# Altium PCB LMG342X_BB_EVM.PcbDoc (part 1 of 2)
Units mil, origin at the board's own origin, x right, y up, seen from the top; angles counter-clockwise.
Board outline 6400 x 3655 mil, 2 copper layers (Top Layer, Bottom Layer), stack 61.2 mil thick; 157 components, 63 nets, 278 pads, 411 vias.
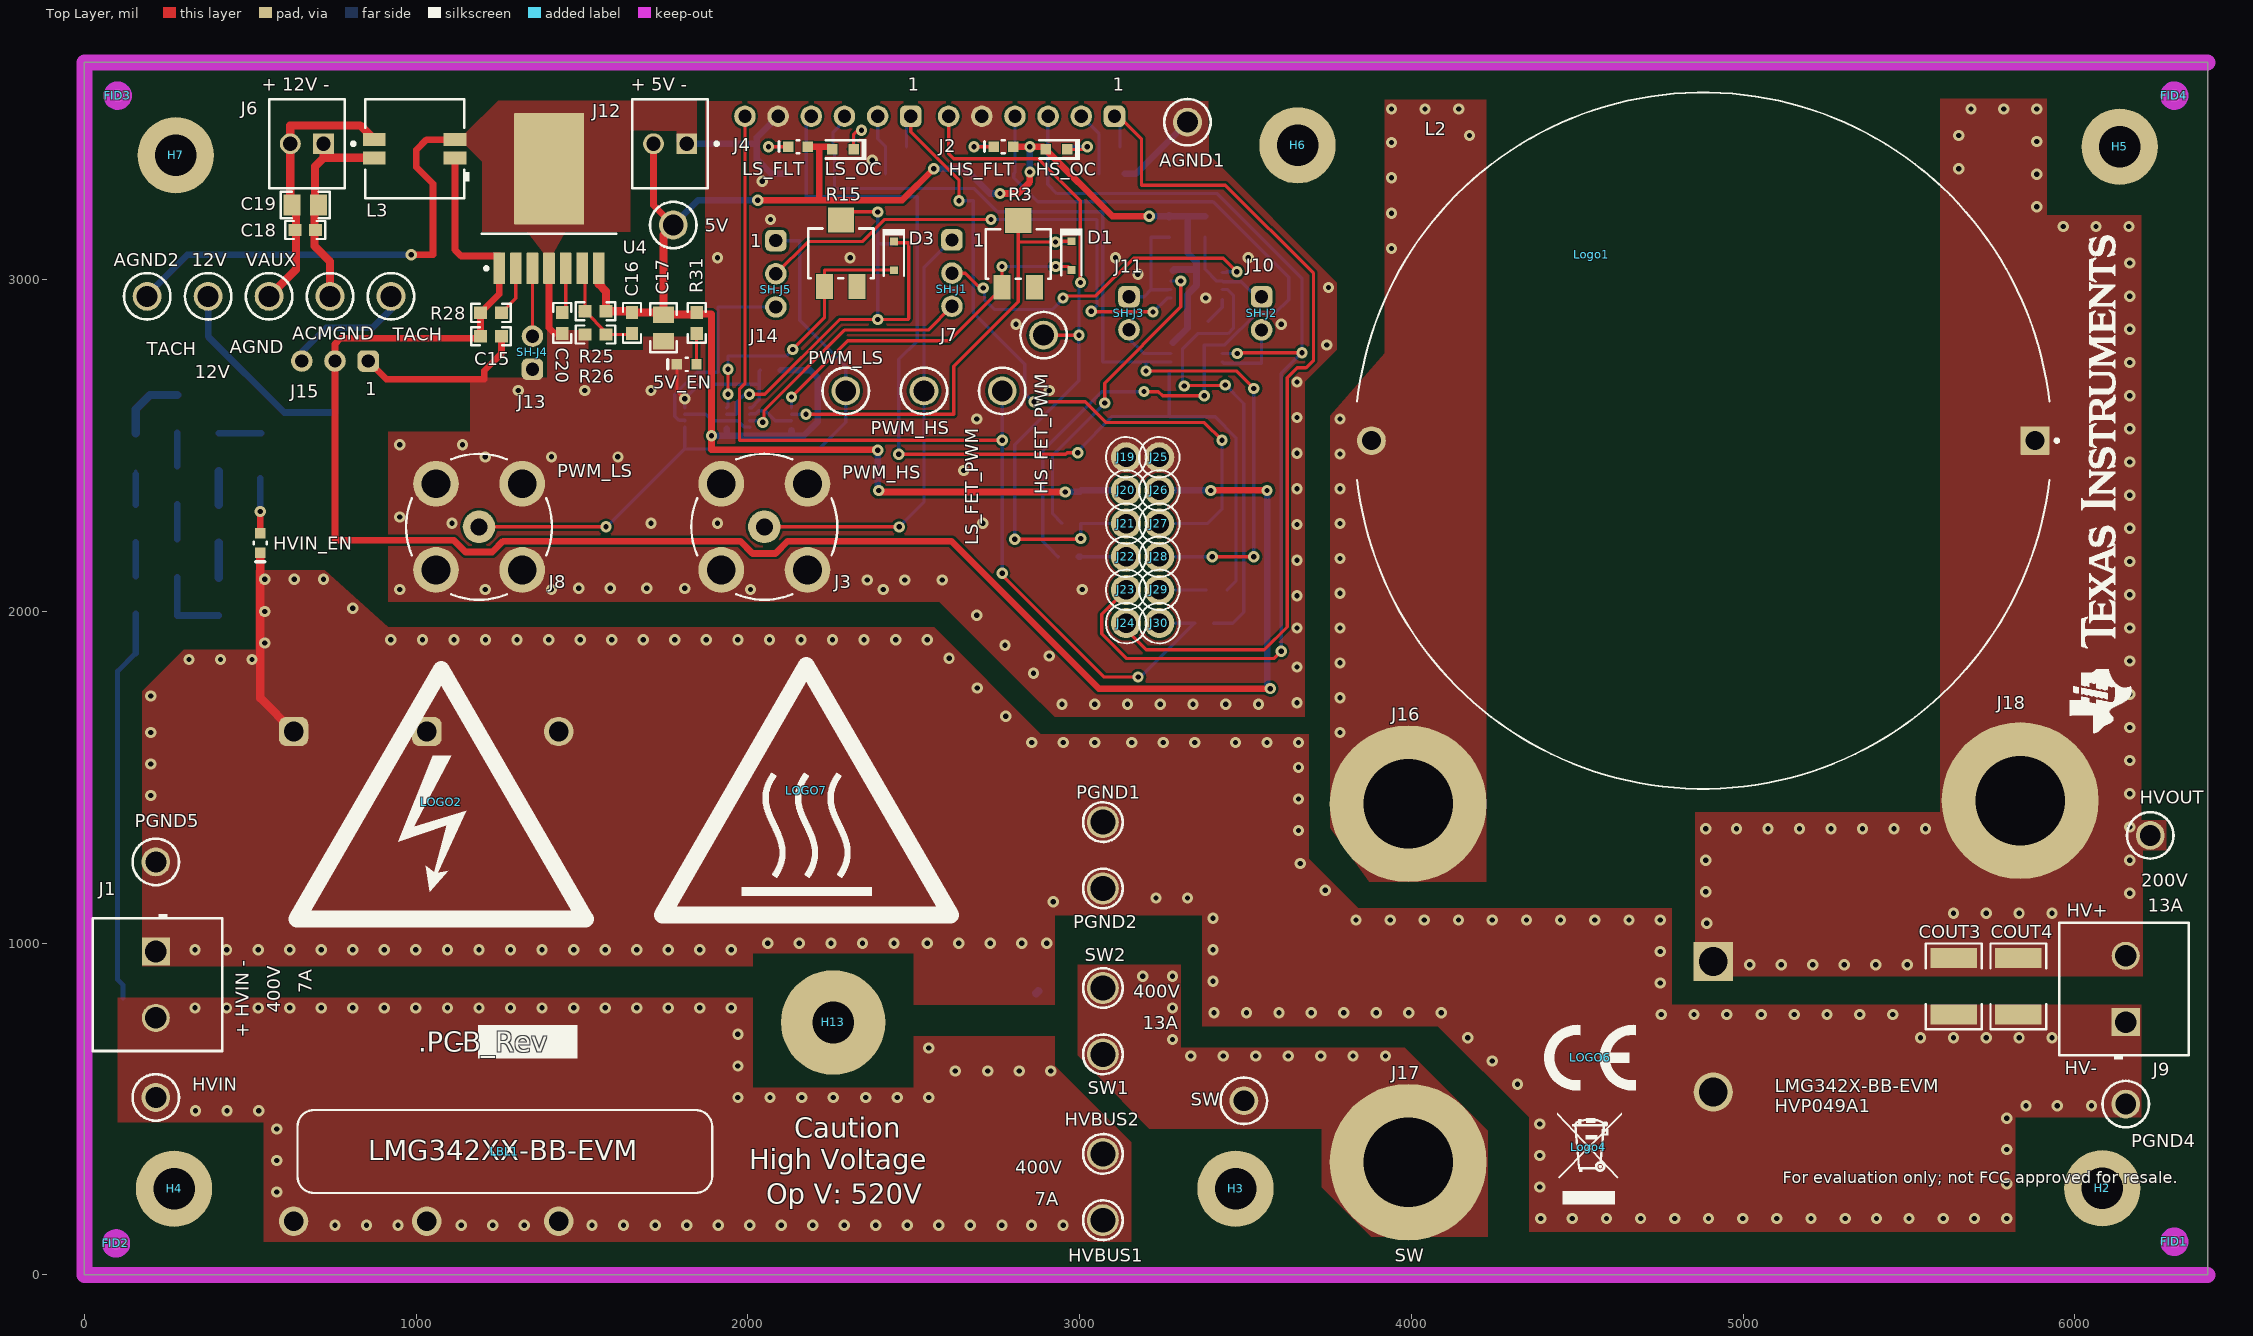
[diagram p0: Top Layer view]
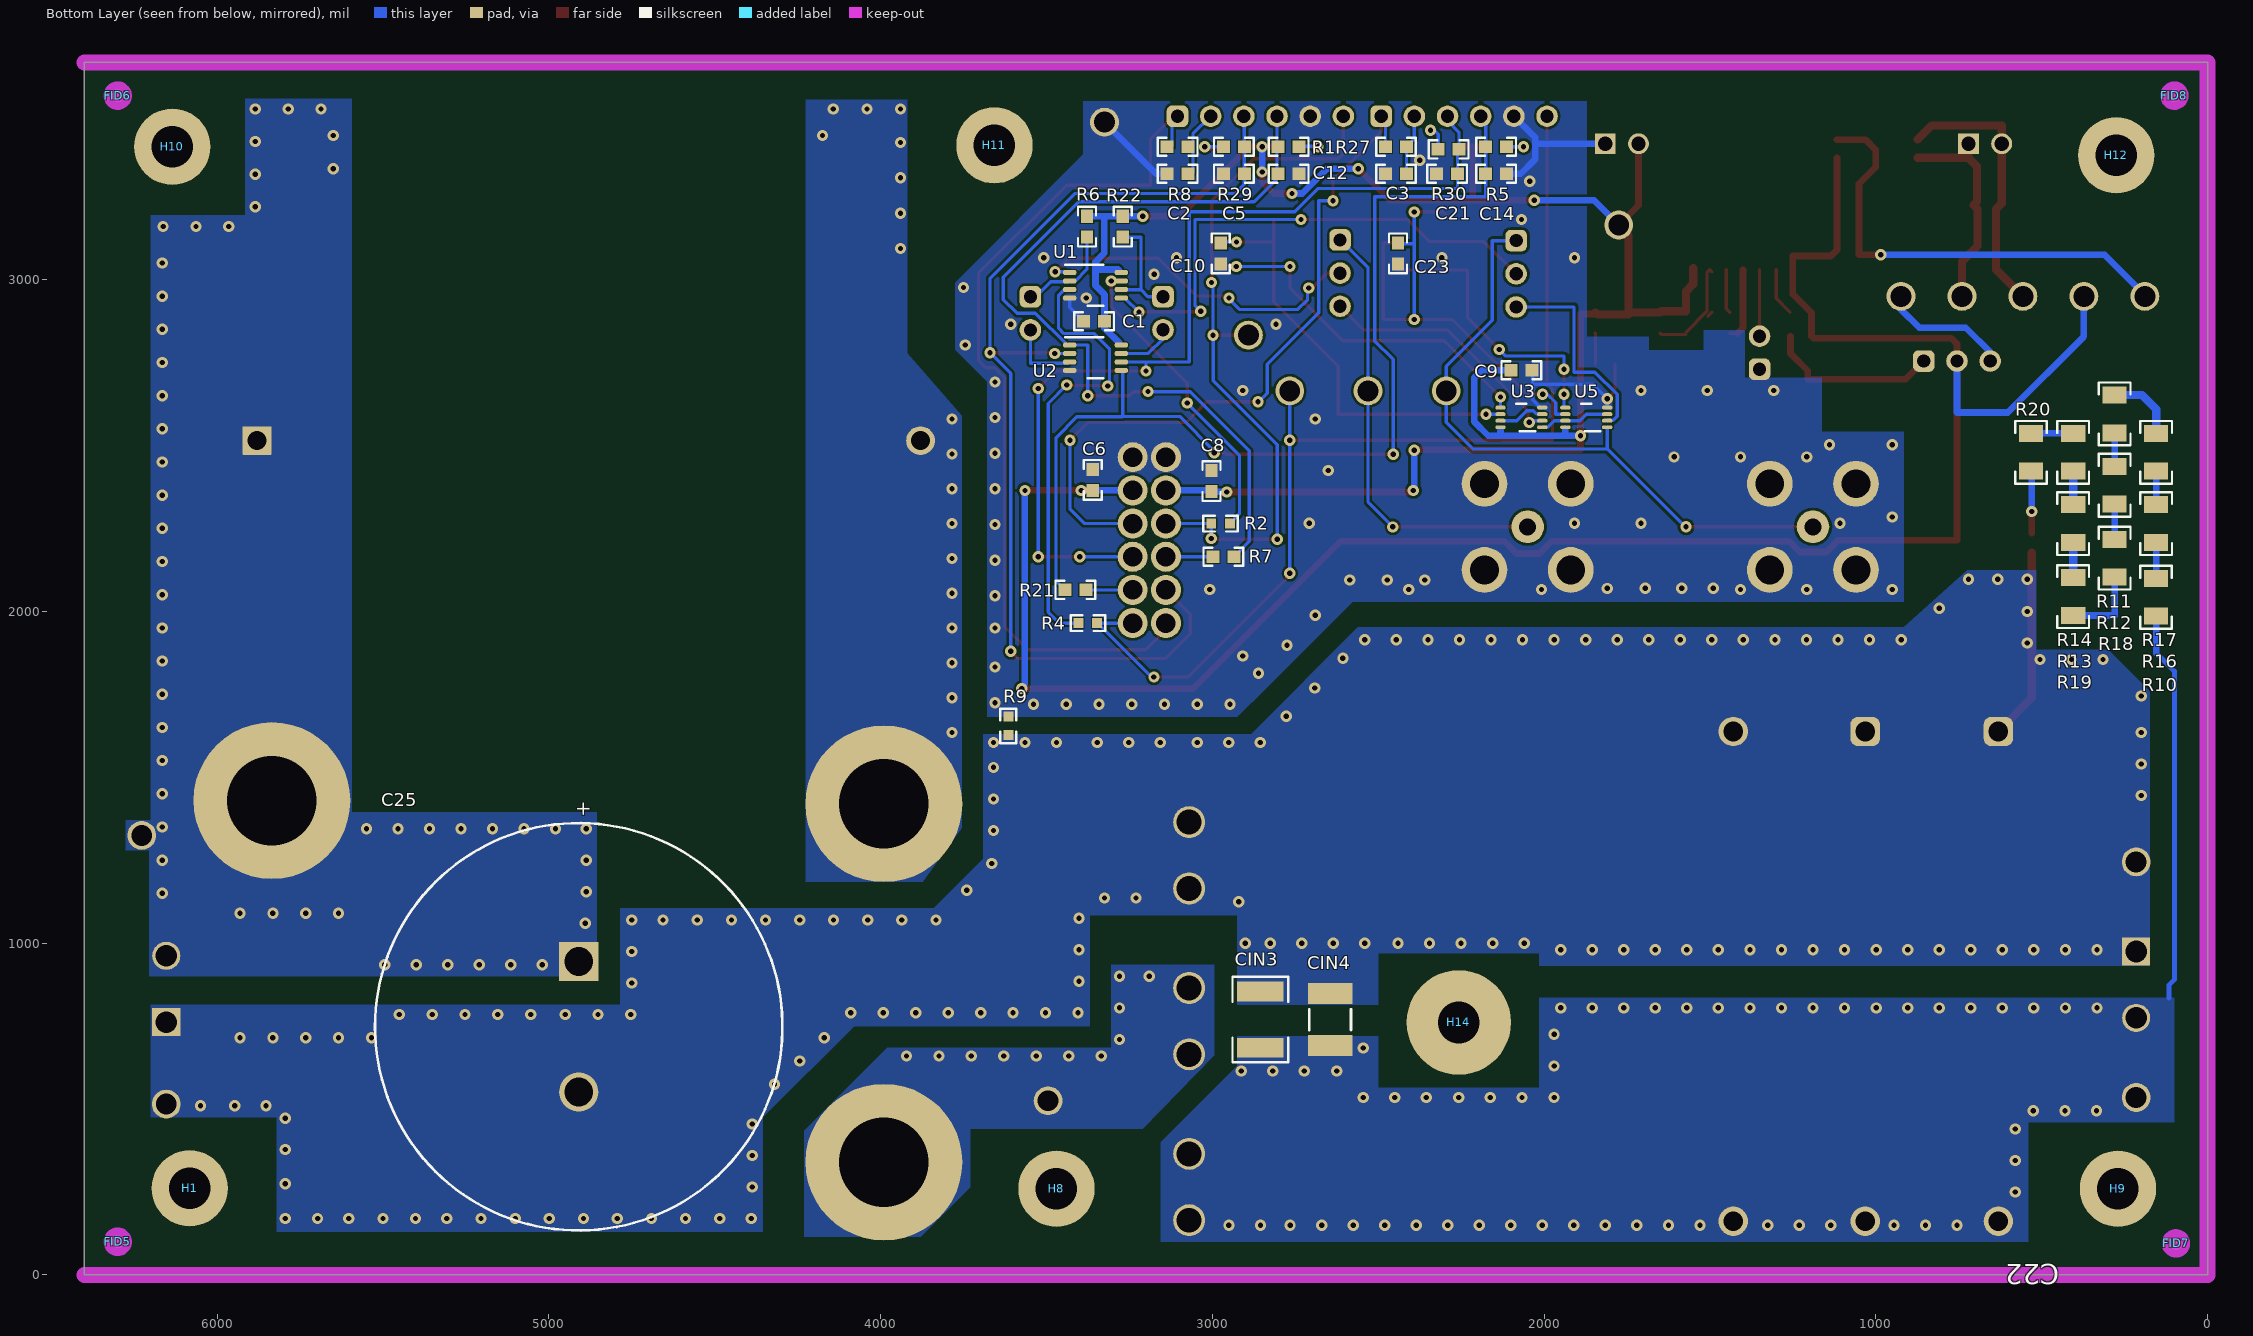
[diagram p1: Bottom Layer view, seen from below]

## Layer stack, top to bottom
Top Solder: solder mask 0.4, Solder Resist, Dk 3.5
Top Layer: signal copper 2.8
Dielectric1: core 55.6, FR-4 High Tg, Dk 4.8
Bottom Layer: signal copper 2.8
Bottom Solder: solder mask 0.4, Solder Resist, Dk 3.5

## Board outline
0,0 6400,0 6400,3655 0,3655

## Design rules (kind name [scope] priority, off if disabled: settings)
AcuteAngle [All] p1: minimum=4.50000000000000E+0001 checktracksonly=FALSE
AssemblyTestPointUsage [All] p1: valid=2
Clearance Clearance_FiducialMark [IsKeepOut and InComponentClass('FiducialMark') vs IsPad and InComponentClass('FiducialMark')] p1: gap=0 ignorepadtopadclearanceinfootprint=FALSE
Clearance Clearance_SIGHEADER [All] p2: gap=7.87 ignorepadtopadclearanceinfootprint=FALSE except(0: Arc-Hole Track-Hole SMDPad-Hole THPad-Hole Via-Hole Fill-Hole Poly-Hole Region-Hole Text-Hole; 4: SMDPad-SMDPad SMDPad-THPad SMDPad-Via SMDPad-Fill SMDPad-Poly SMDPad-Region SMDPad-Text)
Clearance Clearance_HV [InNetClass('HV') vs NOT InNetClass('HV')] p3: gap=60 ignorepadtopadclearanceinfootprint=FALSE except(0: Arc-Hole Track-Hole SMDPad-Hole THPad-Hole Via-Hole Fill-Hole Poly-Hole Region-Hole Text-Hole)
Clearance Clearance_SW [InNetClass('SW') vs NOT InNetClass('SW')] p4: gap=60 ignorepadtopadclearanceinfootprint=FALSE except(0: Arc-Hole Track-Hole SMDPad-Hole THPad-Hole Via-Hole Fill-Hole Poly-Hole Region-Hole Text-Hole)
Clearance Clearance_ISO [InNetClass('Iso1') vs NOT InNetClass('Iso1')] p5: gap=7.87 ignorepadtopadclearanceinfootprint=FALSE except(0: Arc-Hole Track-Hole SMDPad-Hole THPad-Hole Via-Hole Fill-Hole Poly-Hole Region-Hole Text-Hole)
Clearance Clearance_Keepouts [((IsTrack Or IsArc) And Not InPoly) And IsFree and IsKeepOut vs ((IsTrack Or IsArc) And Not InPoly) And IsFree and IsKeepOut] p6: gap=0 ignorepadtopadclearanceinfootprint=FALSE
Clearance Clearance_BoardEdge_MountingHoles [OnCopper and InComponentClass('Mounting Holes') vs IsKeepOut] p7: gap=40 ignorepadtopadclearanceinfootprint=FALSE except(0: Arc-Hole Track-Hole SMDPad-Hole THPad-Hole Via-Hole Fill-Hole Poly-Hole Region-Hole Text-Hole)
Clearance Clearance_BoardEdge [OnCopper and Not InComponentClass('Logo') and not InComponentClass('FiducialMark') and not InRegion(1000,500,4000,800) and Not IsKeepout vs IsKeepOut] p8: gap=75 ignorepadtopadclearanceinfootprint=FALSE except(0: Arc-Hole Track-Hole SMDPad-Hole THPad-Hole Via-Hole Fill-Hole Poly-Hole Region-Hole Text-Hole)
Clearance [All] p9: gap=7.87 ignorepadtopadclearanceinfootprint=FALSE except(0: Arc-Hole Track-Hole SMDPad-Hole THPad-Hole Via-Hole Fill-Hole Poly-Hole Region-Hole Text-Hole)
ComponentClearance ComponentClearance_STANDOFF [All] p1: gap=0 collisioncheckmode=3 verticalgap=0 showdistances=FALSE
ComponentClearance ComponentClearance_MountingHoles_FiducialMarks [InComponentClass('Mounting Holes') vs InComponentClass('FiducialMark')] p2: gap=50 collisioncheckmode=3 verticalgap=10 showdistances=FALSE
ComponentClearance ComponentClearance_Shunt [InComponentClass('Header') vs InComponentClass('Shunt')] p3: gap=0 collisioncheckmode=3 verticalgap=0 showdistances=FALSE
ComponentClearance ComponentClearance_Logo [InComponentClass('Logo')] p4: gap=50 collisioncheckmode=3 verticalgap=10 showdistances=FALSE
ComponentClearance ComponentClearance_PowerConnector [(HasFootprint('Mill-Max_0312-0-15-15-34-27-10-0') or HasFootprint('Molex_0448120024'))] p5: gap=0 collisioncheckmode=3 verticalgap=0 showdistances=FALSE
ComponentClearance ComponentClearance_ScrewToNut [(HasFootprint('NY PMS 440 0025 PH')) vs (HasFootprint('Keystone_1902C'))] p6: gap=5 collisioncheckmode=3 verticalgap=10 showdistances=FALSE
ComponentClearance ComponentClearance_MountingHoles [InComponentClass('Mounting Holes')] p7: gap=50 collisioncheckmode=3 verticalgap=100000 showdistances=FALSE
ComponentClearance ComponentClearance_SmallPassives [HasFootprint('0201*') or HasFootprint('0402*') or HasFootprint('0508') or HasFootprint('0603*') or HasFootprint('0612') or HasFootprint('0805*') or HasFootprint('0815*') or HasFootprint('0830*') or HasFootprint('1206*') or HasFootprint('1210*') or HasFootprint('1808*') or HasFootprint('1812*') or HasFootprint('1825*') or HasFootprint('2010*') or HasFootprint('2220*') or HasFootprint('2225*') or HasFootprint('2512*') or HasFootprint('2728*') or HasFootprint('3518*') vs HasFootprint('0201*') or HasFootprint('0402*') or HasFootprint('0508') or HasFootprint('0603*') or HasFootprint('0612') or HasFootprint('0805*') or HasFootprint('0815*') or HasFootprint('0830*') or HasFootprint('1206*') or HasFootprint('1210*') or HasFootprint('1808*') or HasFootprint('1812*') or HasFootprint('1825*') or HasFootprint('2010*') or HasFootprint('2220*') or HasFootprint('2225*') or HasFootprint('2512*') or HasFootprint('2728*') or HasFootprint('3518*')] p8: gap=20 collisioncheckmode=3 verticalgap=10 showdistances=FALSE
ComponentClearance ComponentClearance_THtoSMT [IsThruComponent vs IsSMTComponent] p9: gap=15.75 collisioncheckmode=3 verticalgap=30 showdistances=FALSE
ComponentClearance ComponentClearance_THtoTH [IsThruComponent vs IsThruComponent] p10: gap=7.87 collisioncheckmode=3 verticalgap=30 showdistances=FALSE
ComponentClearance [All] p11: gap=10 collisioncheckmode=3 verticalgap=10 showdistances=FALSE
DiffPairsRouting [All] p1: maxlimit=100 minlimit=10 mostfreqgap=10 toplayer_minwidth=15 toplayer_maxwidth=15 toplayer_prefwidth=15 bottomlayer_minwidth=15 bottomlayer_maxwidth=15 bottomlayer_prefwidth=15 maxuncoupledlength=1000
FabricationTestPointUsage TestPointUsage [All] p1: valid=2 allowmultiple=FALSE
FabricationTestpoint Testpoint [All] p1: side=3 testpointundercomponent=TRUE minsize=40 maxsize=100 preferedsize=60 minholesize=0 maxholesize=40 preferedholesize=32 testpointgrid=1 allowsidetop=TRUE allowsidebottom=TRUE usegrid=TRUE gridtolerance=0.01
FanoutControl Fanout_LCC [IsLCC] p1: bgadir=Out bgaviamode=Centered fanoutstyle=Auto fanoutdirection=Alternating viagrid=1 // Fanout_LCC (Default Rule)
FanoutControl Fanout_BGA [IsBGA] p2: bgadir=Out bgaviamode=Centered fanoutstyle=Auto fanoutdirection=Alternating viagrid=1 // Fanout_BGA (Default Rule)
FanoutControl Fanout_Default [All] p4: bgadir=Out bgaviamode=Centered fanoutstyle=Auto fanoutdirection=Alternating viagrid=1 // Fanout_Default (Default Rule)
FanoutControl Fanout_Small [(CompPinCount < 5)] p5: bgadir=Out bgaviamode=Centered fanoutstyle=Auto fanoutdirection=OutThenIn viagrid=1 // Fanout_Small (Default Rule)
Height [All] p1: minheight=0 maxheight=5000 prefheight=500
HoleSize [All] p1: absolutevalues=TRUE maxlimit=300 minlimit=8 maxpercent=80.000 minpercent=20.000
MinimumAnnularRing MinimumAnnularRing_ThermalPadVias [IsVia and InAnyComponent] p1: minimumring=5.91
MinimumAnnularRing [All] p2: minimumring=3
MinimumSolderMaskSliver MinimumSolderMaskSliver_Logo [InComponentClass('Logo') vs InComponentClass('Logo')] p1: minsoldermaskwidth=0
MinimumSolderMaskSliver [All] p2: minsoldermaskwidth=0
PlaneConnect [All] p1: planeconnectstyle=Direct reliefexpansion=10 reliefentries=4 reliefconductorwidth=10 reliefairgap=10
PolygonConnect [All] p1: connectstyle=Direct reliefconductorwidth=10 reliefentries=4 polygonreliefangle="90 Angle" airgapwidth=10
RoutingVias ThermalPadVias [IsVia and InAnyComponent] p1: holewidth=7.87 width=19.68 viastyle="Through Hole" minholewidth=7.87 minwidth=19.68 maxholewidth=12.99 maxwidth=23.62
RoutingVias [All] p2: holewidth=16 width=34 viastyle="Through Hole" minholewidth=7.87 minwidth=19 maxholewidth=40 maxwidth=65
SilkToBoardRegionClearance [Not ((IsComment or IsDesignator) And (Hide <> 'False')) and not InRegion(1000,500,4000,800)] p1:
SilkToSilkClearance SilkToSilkClearance_Pb-FreeLogo [(HasFootprint('Pb-Free_Overlay_Medium') OR HasFootprint('Pb-Free_Overlay_Small')) vs (HasFootprint('Pb-Free_Overlay_Medium') OR HasFootprint('Pb-Free_Overlay_Small'))] p1: silktosilkclearance=0
SilkToSilkClearance [All] p2: silktosilkclearance=0
SilkToSolderMaskClearance "Silk to Solder Mask Opening" [All] p1: minsilkscreentomaskgap=0 clearancetoexposedcopper=FALSE
SolderMaskExpansion [All] p1: expansion=1.97 istentingtop=FALSE
Width [All] p1: maxlimit=100 minlimit=6 preferedwidth=10 checkconnectedcopper=TRUE
14 further rules are at their usual default settings.

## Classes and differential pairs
net class SigHeader: 5V 12V AGND HS_FET_OCZ_2 HS_FET_PWM_2 HS_FET_TEMP_2 LS_FET_OCZ_2 LS_FET_PWM_2 LS_FET_TEMP_2 NetJ22_1 NetJ29_1
component class FiducialMark: FID1 FID2 FID3 FID4 FID5 FID6 FID7 FID8
net class SW: NetJ16_1 SW_2
net class LV: PGND
net class Iso1: 5V 12V AGND HS_FET_FAULTZ_2 HS_FET_OCZ_2 HS_FET_PWM_2 HS_FET_TEMP_2 HS_FET_TEMP_FILT_2 LS_FET_FAULTZ_2 LS_FET_OCZ_2 LS_FET_PWM_2 LS_FET_TEMP_2 LS_FET_TEMP_FILT_2 Net5V_EN_1 NetACMGND_1 NetC10_1 NetC16_2 NetC20_1 NetC23_1 NetD1_2 NetD3_2 NetHS_FLT_2 NetHS_OC_2 NetJ7_2 NetJ7_3 NetJ10_1 NetJ10_2 NetJ11_1 NetJ11_2 NetJ13_2 NetJ14_2 NetJ14_3 NetJ22_1 NetJ29_1 NetLS_FLT_2 NetLS_OC_2 NetR2_1 NetR3_3 NetR4_1 NetR15_3 NetR28_2 NetU3_1 NetU3_3 PGND PWM_HS_2 PWM_LS_2 TACH_2 VAUX_2
net class HV: HVBUS_2 HVOUT_2 NetHVIN_EN_1 NetR10_1 NetR11_1 NetR11_2 NetR12_1 NetR13_1 NetR13_2 NetR14_1 NetR16_1 NetR18_1 PGND
component class Shunt: SH-J1 SH-J2 SH-J3 SH-J4 SH-J5
component class Label: LBL1
component class AssemblyNote: ZZ1 ZZ2 ZZ3 ZZ4
component class LMG342XX_BB_EVM_APL_Hardware: FID1 FID2 FID3 FID4 FID5 FID6 FID7 FID8 H1 H2 H3 H4 H5 H6 H7 H8 H9 H10 H11 H12 H13 H14 LBL1 Logo1 LOGO2 Logo3 Logo4 LOGO6 LOGO7 ZZ1 ZZ2 ZZ3 ZZ4
component class Logo: Logo1
component class "Mounting Holes": H13
component class Header: J2 J4 J7 J10 J11 J13 J14 J15
component class LMG342XX_BB_EVM_APL: 5V 5V_EN 12V ACMGND AGND1 AGND2 AGND3 C1 C2 C3 C5 C6 C8 C9 C10 C12 C14 C15 C16 C17 C18 C19 C20 C21 C22 C23 C25 CIN3 CIN4 COUT3 COUT4 D1 D2 D3 HS_FET_PWM HS_FLT HS_OC HVBUS1 HVBUS2 HVIN HVIN! HVIN_EN HVIN_GD HVOUT J1 J2 J3 J4 J5 J6 J7 J8 J9 J10 J11 J12 J13 J14 J15 J16 J17 J18 J19 J20 J21 J22 J23 J24 J25 J26 J27 J28 J29 J30 L2 L3 LS_FET_PWM LS_FLT LS_OC PGND1 PGND2 PGND4 PGND5 PWM_HS PWM_LS R1 R2 R3 R4 R5 R6 R7 R8 R9 R10 R11 R12 R13 R14 R15 R16 R17 R18 R19 R20 R21 R22 R25 R26 R27 R28 R29 R30 R31 SH-J1 SH-J2 SH-J3 SH-J4 SH-J5 SW SW1 SW2 TACH U1 U2 U3 U4 U5 U8 VAUX

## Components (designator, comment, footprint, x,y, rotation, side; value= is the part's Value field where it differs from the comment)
5V "5005" KEYSTONE5005 1775,3165 r0 top
5V_EN "LG L29K-G2J1-24-Z" "LG L29K_GREEN" 1815.47,2745 r180 top value=Green
12V "5005" KEYSTONE5005 372.68,2950 r0 top
ACMGND "5006" KEYSTONE5006 740.18,2950 r90 top
AGND1 "5006" KEYSTONE5006 3325,3475 r90 top
AGND2 "5006" KEYSTONE5006 188.93,2950 r90 top
C1 "CGA3E1X7R1E105K080AD" 0603 3356.5,2875 r180 bottom value=1uF
C2 "GRM1885C1H162JA01D" 0603 3105,3319.51 r180 bottom value=1600pF
C3 "GRM1885C1H162JA01D" 0603 2446.34,3319.51 r180 bottom value=1600pF
C5 "GRM1885C1H390JA01D" 0603 2935,3319.58 r0 bottom value=39pF
C6 "CGA3E1X7R1E105K080AD" 0603 3360.72,2396.5 r90 bottom value=1uF
C8 "CGA3E1X7R1E105K080AD" 0603 3002.47,2393.29 r90 bottom value=1uF
C9 "CGA3E1X7R1E105K080AD" 0603 2068.32,2727.28 r0 bottom value=1uF
C10 "GRM1885C1H390JA01D" 0603 2975,3079.51 r270 bottom value=39pF
C12 "GRM1885C1H390JA01D" 0603 2770,3319.58 r180 bottom value=39pF
C14 "GRM1885C1H390JA01D" 0603 2144.7,3319.58 r180 bottom value=39pF
C15 "GRT188R61E106ME13D" 0603 1225.47,2830 r0 top value=10uF
C16 "885012206091" 0603 1650.47,2870 r270 top value=0.022uF
C17 "GRM21BR60J107M" 0805_HV 1745.47,2855 r270 top value=100uF
C18 "CGA3E1X7R1E105K080AD" 0603 665.47,3150 r0 top value=1uF
C19 "CL21A106KAFN3NE" 0805_HV 665.47,3225 r0 top value=10uF
C20 "885012206091" 0603 1440.47,2870 r270 top value=0.022uF
C21 "GRM1885C1H390JA01D" 0603 2292.5,3319.58 r0 bottom value=39pF
C22 "FE37M6C0206KB" FE37M 1030,900 r270 bottom value=20uF
C23 "GRM1885C1H390JA01D" 0603 2440.39,3079.51 r270 bottom value=39pF
C25 "LGN2X151MELB50" NICHICON_3000X5000_SNAP 4910,748.15 r270 bottom value=150uF
CIN3 "GRM43DR72J104KW01L" 1812_HV 2855,770 r90 bottom value=0.1uF
CIN4 "GRM43DR72J104KW01L" 1812 2645,770 r90 bottom value=0.1uF
COUT3 "GRM43DR72J104KW01L" 1812_HV 5635,870 r270 top value=0.1uF
COUT4 "GRM43DR72J104KW01L" 1812_HV 5830,870 r270 top value=0.1uF
D1 "BAT54WS-7-F" SOD-323 2975,3072.8 r270 top value=30V
D3 "BAT54WS-7-F" SOD-323 2440,3071.77 r270 top value=30V
FID1 "Fiducial" FIDUCIAL10-20 6300,100 r0 top
FID2 "Fiducial" FIDUCIAL10-20 95,95 r90 top
FID3 "Fiducial" FIDUCIAL10-20 100,3555 r90 top
FID4 "Fiducial" FIDUCIAL10-20 6300,3555 r90 top
FID5 "Fiducial" FIDUCIAL10-20 6300,100 r90 bottom
FID6 "Fiducial" FIDUCIAL10-20 6300,3555 r90 bottom
FID7 "Fiducial" FIDUCIAL10-20 95,95 r90 bottom
FID8 "Fiducial" FIDUCIAL10-20 100,3555 r90 bottom
H1 "3484" KEYSTONE_3484 6083,261 r180 bottom
H2 "PMSSS 440 0025 PH" B_F_PMSSS4400025PH 6083,261 r0 top
H3 "PMSSS 440 0025 PH" B_F_PMSSS4400025PH 3469.91,260 r0 top
H4 "PMSSS 440 0025 PH" B_F_PMSSS4400025PH 270,260 r0 top
H5 "PMSSS 440 0025 PH" B_F_PMSSS4400025PH 6135,3401.06 r0 top
H6 "PMSSS 440 0025 PH" B_F_PMSSS4400025PH 3656.87,3405 r0 top
H7 "PMSSS 440 0025 PH" B_F_PMSSS4400025PH 274.99,3375.01 r0 top
H8 "3484" KEYSTONE_3484 3469.92,260 r180 bottom
H9 "3484" KEYSTONE_3484 270,260 r180 bottom
H10 "3484" KEYSTONE_3484 6135,3401.06 r180 bottom
H11 "3484" KEYSTONE_3484 3656.88,3405 r180 bottom
H12 "3484" KEYSTONE_3484 275,3375 r180 bottom
H13 "NY PMS 440 0025 PH" "NY PMS 440 0025 PH" 2257,761 r0 top
H14 "1902C" KEYSTONE_1902C 2256.77,761.01 r180 bottom
HS_FET_PWM "5007" KEYSTONE5007 2891.38,2833.13 r90 top
HS_FLT "LS L29K-G1J2-1-Z" "LS L29K_RED" 2770,3401.06 r180 top value=Red
HS_OC "SML-E12Y8WT86" SML-E1_YELLOW 2930,3392.93 r180 top value=Yellow
HVBUS1 "0312-0-15-15-34-27-10-0" MILL-MAX_0312-0-15-15-34-27-10-0 3070.01,165 r90 top
HVBUS2 "0312-0-15-15-34-27-10-0" MILL-MAX_0312-0-15-15-34-27-10-0 3070.01,365 r90 top
HVIN "5005" KEYSTONE5005 215,535 r0 top
HVIN_EN "LG L29K-G2J1-24-Z" "LG L29K_GREEN" 530.06,2206.79 r270 top value=Green
HVOUT "5005" KEYSTONE5005 6227.33,1325 r90 top
J1 "0395443002" MOLEX_0395443002 215,875 r270 top
J2 "TSW-106-07-G-S" TSW-106-07-G-S 2855,3492.93 r180 top
J3 "112404" AMPHENOL_112404 2049.53,2255.26 r0 top
J4 "TSW-106-07-G-S" TSW-106-07-G-S 2241,3492.93 r180 top
J6 "282834-2" TEC_282834-2 670.47,3410 r180 top
J7 "TSW-103-07-G-S" TSW-103-07-G-S 2615,3020 r270 top
J8 "112404" AMPHENOL_112404 1189.45,2255.26 r0 top
J9 "0395443002" MOLEX_0395443002 6153.45,862.04 r90 top
J10 "TSW-102-07-G-S" TSW-102-07-G-S 3548.4,2898.76 r270 top
J11 "TSW-102-07-G-S" TSW-102-07-G-S 3148.7,2899.13 r270 top
J12 "282834-2" TEC_282834-2 1765.47,3410 r180 top
J13 "TSW-102-07-G-S" TSW-102-07-G-S 1350.47,2780 r90 top
J14 "TSW-103-07-G-S" TSW-103-07-G-S 2084.2,3018.02 r270 top
J15 "TSW-103-07-G-S" TSW-103-07-G-S 755.18,2755 r180 top
J16 "3267" POMONA_3267 3990,1420 r0 top
J17 "3267" POMONA_3267 3990,340 r0 top
J18 "3267" POMONA_3267 5835,1430 r0 top
J19 "0305-2-15-15-47-27-10-0" FP-0305-2-15-15-47-27-10-0_CONN_PIN_RCPT-MFG 3140,2465 r90 top
J20 "0305-2-15-15-47-27-10-0" FP-0305-2-15-15-47-27-10-0_CONN_PIN_RCPT-MFG 3140,2365 r0 top
J21 "0305-2-15-15-47-27-10-0" FP-0305-2-15-15-47-27-10-0_CONN_PIN_RCPT-MFG 3140,2265 r0 top
J22 "0305-2-15-15-47-27-10-0" FP-0305-2-15-15-47-27-10-0_CONN_PIN_RCPT-MFG 3140,2165 r0 top
J23 "0305-2-15-15-47-27-10-0" FP-0305-2-15-15-47-27-10-0_CONN_PIN_RCPT-MFG 3140,2065 r0 top
J24 "0305-2-15-15-47-27-10-0" FP-0305-2-15-15-47-27-10-0_CONN_PIN_RCPT-MFG 3140,1965 r0 top locked
J25 "0305-2-15-15-47-27-10-0" FP-0305-2-15-15-47-27-10-0_CONN_PIN_RCPT-MFG 3240,2465 r0 top
J26 "0305-2-15-15-47-27-10-0" FP-0305-2-15-15-47-27-10-0_CONN_PIN_RCPT-MFG 3240,2365 r0 top
J27 "0305-2-15-15-47-27-10-0" FP-0305-2-15-15-47-27-10-0_CONN_PIN_RCPT-MFG 3240,2265 r0 top
J28 "0305-2-15-15-47-27-10-0" FP-0305-2-15-15-47-27-10-0_CONN_PIN_RCPT-MFG 3240,2165 r0 top
J29 "0305-2-15-15-47-27-10-0" FP-0305-2-15-15-47-27-10-0_CONN_PIN_RCPT-MFG 3240,2065 r0 top
J30 "0305-2-15-15-47-27-10-0" FP-0305-2-15-15-47-27-10-0_CONN_PIN_RCPT-MFG 3240,1965 r0 top
L2 "750317345" FP-750317345_PTH_D53MM34-MFG 4879.75,2515 r180 top value=570uH
L3 "DRQ73-470-R" DRQ73 995.47,3395 r180 top value=47uH
LBL1 "Size: 1.25\" x 0.25\"" LABEL_1250X250 1267,372.1 r0 top
Logo1 "Texas Instruments" TI_HORIZONTAL_OVERLAY_MEDIUM 4544,3075.4 r90 top
LOGO2 "DANGER HIGH VOLTAGE" IEC_HIGHVOLTAGE_LARGE 1075.28,1425 r0 top
Logo3 "FCC disclaimer" FCC_DISCLAIMER 3970,-480 r0 top
Logo4 "WEEE logo" WEEE_MINIMUM 4535,385 r0 top
LOGO6 "CE Mark" CE_MARK_5MM 4538.65,655 r0 top
LOGO7 "CAUTION HOT SURFACE" IEC_HOTSURFACE_LARGE 2176.2,1460 r0 top
LS_FET_PWM "5007" KEYSTONE5007 2766.51,2665 r90 top
LS_FLT "LS L29K-G1J2-1-Z" "LS L29K_RED" 2151,3401.06 r180 top value=Red
LS_OC "SML-E12Y8WT86" SML-E1_YELLOW 2286,3392.93 r180 top value=Yellow
PGND1 "0312-0-15-15-34-27-10-0" MILL-MAX_0312-0-15-15-34-27-10-0 3070,1365 r90 top
PGND2 "0312-0-15-15-34-27-10-0" MILL-MAX_0312-0-15-15-34-27-10-0 3070,1165 r90 top
PGND4 "5006" KEYSTONE5006 6153.45,515 r90 top
PGND5 "5006" KEYSTONE5006 215,1245 r90 top
PWM_HS "5007" KEYSTONE5007 2530.76,2665 r90 top
PWM_LS "5007" KEYSTONE5007 2295,2665 r90 top
R1 "CRCW06033K30JNEA" 0603 2770,3401.05 r180 bottom value=3.3k
R2 "CRCW06030000Z0EA" 0603_HV 2975.36,2265 r0 bottom locked value=0
R3 "3224X-1-502E" TRIM_3224X 2815,3078.02 r90 top value=5K
R4 "CRCW06030000Z0EA" 0603_HV 3375.31,1965.01 r180 bottom value=0
R5 "CRCW06033K30JNEA" 0603 2144.7,3401.06 r180 bottom value=3.3k
R6 "CRCW0603100KJNEAC" 0603 3377.9,3160 r270 bottom value=100k
R7 "CRCW0603100RJNEA" 0603 2966.5,2165 r180 bottom locked value=100
R8 "RC0603FR-07105KL" 0603 3105,3400.99 r180 bottom value=105k
R9 "CRCW06030000Z0EA" 0603_HV 3615,1655 r270 bottom value=0
R10 "CRCW120630K0JNEA" 1206 155,2042.91 r270 bottom value=30k
R11 "CRCW120630K0JNEA" 1206 279.92,2595.53 r270 bottom value=30k
R12 "CRCW120630K0JNEA" 1206 279.92,2380.53 r90 bottom value=30k
R13 "CRCW120630K0JNEA" 1206 404.92,2264.86 r90 bottom value=30k
R14 "CRCW120630K0JNEA" 1206 404.92,2479.86 r270 bottom value=30k
R15 "3224X-1-502E" TRIM_3224X 2280,3079.61 r90 top value=5K
R16 "CRCW120630K0JNEA" 1206 154.92,2264.86 r270 bottom value=30k
R17 "CRCW120630K0JNEA" 1206 154.92,2479.86 r90 bottom value=30k
R18 "CRCW120630K0JNEA" 1206 279.92,2160.53 r90 bottom value=30k
R19 "CRCW120630K0JNEA" 1206 404.92,2044.86 r90 bottom value=30k
R20 "CRCW120630K0JNEA" 1206 532.05,2480 r90 bottom value=30k
R21 "CRCW0603100RJNEA" 0603 3412.83,2065 r0 bottom locked value=100
R22 "CRCW0603100KJNEAC" 0603 3270,3160 r90 bottom value=100k
R25 "RC0603FR-076K2L" 0603 1540.47,2905 r0 top value=6.20k
R26 "RC0603FR-071K18L" 0603 1540.47,2835 r0 top value=1.18k
R27 "RC0603FR-07105KL" 0603 2446.34,3400.99 r180 bottom value=105k
R28 "RT0603BRD0733K2L" 0603 1225.47,2900 r0 top value=33.2k
R29 "CRCW06033K30JNEA" 0603 2935,3401.05 r0 bottom value=3.3k
R30 "CRCW06033K30JNEA" 0603 2287.97,3392.93 r0 bottom value=3.3k
R31 "CRCW06031K60JNEA" 0603 1845.47,2870 r90 top value=1.6k
SH-J1 "SNT-100-BK-G" SNT-100-BK-G 2615,2971.55 r90 top value=1x2
SH-J2 "SNT-100-BK-G" SNT-100-BK-G 3548.4,2898.76 r270 top value=1x2
SH-J3 "SNT-100-BK-G" SNT-100-BK-G 3148.7,2899.39 r270 top value=1x2
SH-J4 "SNT-100-BK-G" SNT-100-BK-G 1350,2781 r90 top value=1x2
SH-J5 "SNT-100-BK-G" SNT-100-BK-G 2083.65,2969.31 r90 top value=1x2
SW "5005" KEYSTONE5005 3495,525 r0 top
SW1 "0312-0-15-15-34-27-10-0" MILL-MAX_0312-0-15-15-34-27-10-0 3070,665 r0 top
SW2 "0312-0-15-15-34-27-10-0" MILL-MAX_0312-0-15-15-34-27-10-0 3070,865 r0 top
TACH "5005" KEYSTONE5005 923.93,2950 r0 top
U1 "SN74LVC2G08IDCTRQ1" DCT0008A_N 3352.24,2983.39 r180 bottom
U2 "SN74LVC2G08IDCTRQ1" DCT0008A_N 3352.24,2765 r180 bottom
U3 "SN74LVC3G14DCUTG4" DCU0008A_N 2068.32,2585 r0 bottom
U4 "LMZ12003EXTTZ/NOPB" NDW0007A_V 1400.47,3245 r90 top
U5 "SN74LVC3G14DCUTG4" DCU0008A_N 1872.67,2585 r0 bottom
VAUX "5005" KEYSTONE5005 556.43,2950 r0 top
ZZ1 "This Assembly Note is for PCB labels only" ASSEMBLYNOTELABEL 790,6325 r0 top
ZZ2 "These assemblies are ESD sensitive, ESD precautions shall be observed." ASSEMBLYNOTE 792,6227.78 r0 top
ZZ3 "These assemblies must be clean and free from flux and all contaminants. Use of no clean flux is not acceptable." ASSEMBLYNOTE 792,6130.89 r0 top
ZZ4 "These assemblies must comply with workmanship standards IPC-A-610 Class 2, unless otherwise specified." ASSEMBLYNOTE 792,6034 r0 top

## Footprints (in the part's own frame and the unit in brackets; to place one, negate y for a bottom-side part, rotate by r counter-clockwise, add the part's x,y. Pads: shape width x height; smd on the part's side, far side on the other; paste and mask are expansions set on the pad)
0603 [mm] "0603 from SM-752 data"
  rect 1x0.95 smd: 1(-0.8,0) 2(0.8,0)
  silkscreen extent -1.52,-0.69 1.52,0.69, body extent -0.87,-0.47 0.87,0.47, height 1
0603_HV [mil] "Ernesto recommended land pattern.  26 mil between pads."
  rect 30x30 smd: 1(-28,0) 2(28,0)
  silkscreen extent -52,-24 52,24, body extent -34,-19 34,19, height 39
0805_HV [mil] "0805 with 30mil clearance between pads"
  rect 50x63 smd: 1(-40,0) 2(40,0)
  silkscreen extent -74,-40 74,40, body extent -43,-29 43,29, height 57
1206 [mm] "1206 from SM-752 data"
  rect 1.3x1.85 smd: 1(-1.45,0) 2(1.45,0)
  silkscreen extent -2.4,-1.21 2.4,1.21, body extent -1.7,-0.9 1.7,0.9, height 1.35
1812 [mm]
  rect 1.6x3.4 smd: 1(-2,0) 2(2,0)
  silkscreen extent -0.8,-1.6 0.8,1.6, body extent -2.4,-1.7 2.4,1.7, height 1.35
1812_HV [mil] "PRG recommended land pattern"
  rect 60x140 smd: 1(-85,0) 2(85,0)
  silkscreen extent -129,-84 129,84, body extent -94,-67 94,67, height 53
AMPHENOL_112404 [mm] "BNC footprint, pins compatible with Amp 5413631-2"
  round 2.5 hole 1.3: 1(0,0)
  round 3.5 hole 2.2: 2(-3.3,3.3) 3(3.3,3.3) 4(3.3,-3.3) 5(-3.3,-3.3)
  silkscreen extent -5.59,-5.59 5.59,5.59, body extent -5.5,-5.5 5.5,5.5, height 13.7
ASSEMBLYNOTE [mil] "Assembly Note"
ASSEMBLYNOTELABEL [mil] "Assembly Note for PCB Labels"
B_F_PMSSS4400025PH [mil] "MACHINE SCREW PAN PHILLIPS 4-40"
  round 230 hole 125: 1(0,0)
  body extent -109,-109 110,110, height 79
CE_MARK_5MM [mil] "Minimum text height for CE Mark"
  silkscreen extent -138,-99 138,99
DCT0008A_N [mm] "TSOP, 8-Leads, Body 3x2.8mm, Pitch 0.65mm, IPC Medium Density"
  oval 1.05x0.4 smd: 1(-1.975,0.975) 2(-1.975,0.325) 3(-1.975,-0.325) 4(-1.975,-0.975) 5(1.975,-0.975) 6(1.975,-0.325) 7(1.975,0.325) 8(1.975,0.975)
  silkscreen extent -2.32,-1.57 0.6,1.58, body extent -2.01,-1.47 2.01,1.48, height 1.3
DCU0008A_N [mm] "TSSOP, 8-Leads, Body 2x2.3mm, Pitch 0.5mm, IPC Medium Density"
  oval 0.8x0.3 smd: 1(-1.6,0.75) 2(-1.6,0.25) 3(-1.6,-0.25) 4(-1.6,-0.75) 5(1.6,-0.75) 6(1.6,-0.25) 7(1.6,0.25) 8(1.6,0.75)
  silkscreen extent -1.05,-1.05 0.38,1.05, body extent -1.56,-1 1.56,1, height 0.9
DRQ73 [mm] "SMD, 4-Leads, Body 7.6x7.6mm"
  rect 1.73x1 smd: 1(-3.085,0.7) 2(-3.085,-0.7) 3(3.085,-0.7) 4(3.085,0.7)
  silkscreen extent -4.2,-3.8 3.8,3.8, body extent -4.01,-3.8 3.93,3.8, height 3.4
FCC_DISCLAIMER [mil]
FE37M [mm] "TH, 4-Leads, Body 42.5x30mm"
  rrect50% 2.25x2.25 hole 1.5: 1(-18.75,-0.05) 1(-18.75,10.15)
  round 2.25 hole 1.5: 2(18.75,-0.05) 2(18.75,10.15) 3(-18.75,-10.15) 4(18.75,-10.15)
  body extent -21.25,-15 21.25,15, height 45.5
FIDUCIAL10-20 [mm]
  round 1 smd mask+0.5: 1(0,0)
  Top Layer keep-out circle w1.178: c0,0 r0.5
FP-0305-2-15-15-47-27-10-0_CONN_PIN_RCPT-MFG [mil]
  round 90.51 hole 59.02 paste-99999 mask+0: 1(0,0)
  silkscreen extent -61,-61 61,61, body extent -49,-49 49,49, height 10
FP-750317345_PTH_D53MM34-MFG [mm]
  rrect5% 2.2x2.2 hole 1.45 paste-2539.97 mask+0: 1(-25.4,0)
  round 2.2 hole 1.45 paste-2539.97 mask+0: 2(25.4,0)
  silkscreen extent -27.2,-26.66 26.5,26.66, body extent -26.77,-26.77 26.77,26.77, height 0.25
IEC_HIGHVOLTAGE_LARGE [mil]
  silkscreen extent -435,-352 435,401
IEC_HOTSURFACE_LARGE [mil]
  silkscreen extent -435,-375 435,378
KEYSTONE5005 [mil] "Keystone Compact loops"
  round 87 hole 63: 1(0,0)
  silkscreen extent -70,-70 70,70, body extent -63,-63 62,63, height 225
KEYSTONE5006 [mil] "Keystone Compact loops"
  round 87 hole 63: 1(0,0)
  silkscreen extent -70,-70 70,70, body extent -63,-63 62,63, height 225
KEYSTONE5007 [mil] "Keystone Compact loops"
  round 87 hole 63: 1(0,0)
  silkscreen extent -70,-70 70,70, body extent -63,-63 62,63, height 225
KEYSTONE_1902C [mil] "Hex Standoff, 4-40 threaded, nylon"
  round 1 on Mech4: 0(0,0)
  body extent -145,-126 146,126, height 501
KEYSTONE_3484 [mil] "1/4 Round Female Standoff"
  body extent -125,-124 125,124, height 2000
LABEL_1250X250 [mil] "Thermal Transfer Labels"
  round 1 on Mech13: 0(0,0)
  silkscreen extent -625,-125 625,125, body extent -625,-125 625,125, height 1
"LG L29K_GREEN" [mm] "OSRAM"
  rect 0.8x0.8 smd paste-0.4: 1(-0.75,0) 2(0.75,0)
  silkscreen extent -0.1,-0.5 1.45,0.5, body extent -0.9,-0.45 0.9,0.45, height 0.67
"LS L29K_RED" [mm] "SMD, 2-Leads, Body 1.3x0.8mm"
  rect 0.8x0.8 smd paste-0.4: 1(-0.75,0) 2(0.75,0)
  silkscreen extent -0.1,-0.5 1.45,0.5, body extent -0.9,-0.45 0.9,0.45, height 0.67
MILL-MAX_0312-0-15-15-34-27-10-0 [mm] "Pin Receptacle, .032-.046\" .075\" Dia, Gold, TH"
  round 2.45 hole 1.905: 1(0,0)
  silkscreen extent -1.52,-1.52 1.52,1.52, body extent -1.15,-1.15 1.16,1.15, height 0.46
MOLEX_0395443002 [mm] "Terminal Block, 5.08mm, 2x1, TH"
  rect 2.15x2.15 hole 1.65: 1(-2.54,0)
  round 2.15 hole 1.65: 2(2.54,0)
  silkscreen extent -5.4,-4.83 5.08,5.08, body extent -5.08,-4.83 5.08,5.08, height 14.48
NDW0007A_V [mm] "D2-PAK, 8-Leads, Body 9.9x10.2mm, Pitch 1.27mm, Lead Span 13.8mm, NSC Recommended"
  rrect11% 2.41x0.89 smd: 1(-5.35,3.81) 2(-5.35,2.54) 3(-5.35,1.27) 4(-5.35,0) 5(-5.35,-1.27) 6(-5.35,-2.54) 7(-5.35,-3.81)
  rrect2% 8.54x5.35 smd: 8(2.28,0)
  silkscreen extent -5.47,-5.15 -2.7,5.15, body extent -2.55,-5.2 7.55,5.2, height 4.67
NICHICON_3000X5000_SNAP [mm]
  rrect3% 3x3 hole 2.2: 1(-5,0)
  round 3 hole 2.2: 2(5,0)
  silkscreen extent -15.6,-15.6 15.6,15.6, body extent -15.5,-15.5 15.49,15.5, height 52.01
"NY PMS 440 0025 PH" [mm] "4-40 nylon screw and mounting hole"
  round 8 hole 3.2: 1(0,0)
  body extent -3.3,-3.3 3.3,3.3, height 2.69
POMONA_3267 [mm] "Standard Uninsulated Banana Jack"
  round 12 hole 6.858: 1(0,0)
  body extent -4.12,-4.82 4.26,4.85, height 2.79
SML-E1_YELLOW [mm] "SMD, 2-Leads, Body 1.6x0.8mm"
  rect 0.8x0.8 smd: 1(0.825,0) 2(-0.825,0)
  silkscreen extent -1.8,-0.8 1.3,0.8, body extent -0.85,-0.45 0.85,0.45, height 0.46
SNT-100-BK-G [mil] "Samtec STEP model"
  round 1 on Mech3: 0(0,0)
  body extent -100,-50 100,50, height 344
SOD-323 [mm] "NXP recommended land pattern"
  rect 0.6x0.6 smd paste-0.05: 1(-1.1,0) 2(1.1,0)
  silkscreen extent -2.06,-0.86 1.53,0.86, body extent -1.3,-0.67 1.3,0.68, height 1.1
TEC_282834-2 [mm] "TEC"
  rect 1.6x1.6 hole 1.1: 1(-1.27,0)
  round 1.6 hole 1.1: 2(1.27,0)
  silkscreen extent -3.66,-3.4 2.9,3.4, body extent -2.77,-3.25 2.77,3.25, height 10.01
TI_HORIZONTAL_OVERLAY_MEDIUM [mil]
  silkscreen extent -1442,-1628 59,-1440
TRIM_3224X [mm] "Bourns"
  rect 1.9x1.3 smd: 1(-2.55,1.25) 3(-2.55,-1.25)
  rect 1.9x2 smd: 2(2.55,0)
  silkscreen extent -1.9,-2.5 1.9,2.5, body extent -1.8,-2.4 1.8,2.4, height 5.31
TSW-102-07-G-S [mm] "Samtec 100mil, 1x2, 230 mil above insulator"
  rrect50% 1.65x1.65 hole 1.016: 1(-1.27,0)
  round 1.65 hole 1.016: 2(1.27,0)
  body extent -2.54,-1.27 2.54,1.27, height 8.38
TSW-103-07-G-S [mm] "Samtec 100mil, 1x3, 230 mil above insulator"
  rrect50% 1.65x1.65 hole 1.016: 1(-2.54,0)
  round 1.65 hole 1.016: 2(0,0) 3(2.54,0)
  body extent -3.81,-1.27 3.81,1.27, height 8.38
TSW-106-07-G-S [mm] "Samtec 100mil, 1x6, 230 mil above insulator"
  rrect50% 1.65x1.65 hole 1.016: 1(-6.35,0)
  round 1.65 hole 1.016: 2(-3.81,0) 3(-1.27,0) 4(1.27,0) 5(3.81,0) 6(6.35,0)
  body extent -7.62,-1.27 7.62,1.27, height 8.38
WEEE_MINIMUM [mil] "WEEElie bin"
  silkscreen extent -95,-172 99,104

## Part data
5V 12V HVIN HVOUT SW TACH VAUX: library part CMP-0055142-1, "Test Point, Compact, Red, TH", Color=Red, Manufacturer=Keystone, Supplier Part Number 1=36-5005-ND
5V_EN HVIN_EN: library part CMP-0002874-2, "LED, Green, SMD", Color=green, Manufacturer=OSRAM, Value1=W, Value2=1.7V
ACMGND AGND1 AGND2 PGND4 PGND5: library part CMP-0055143-1, "Test Point, Compact, Black, TH", Color=Black, Manufacturer=Keystone, Supplier Part Number 1=36-5006-ND
C1 C6 C8 C9 C18: library part CMP-0082523-1, "CAP, CERM, 1 µF, 25 V,+/- 10%, X7R, AEC-Q200 Grade 1, 0603", Cap_Case=0603, Manufacturer=TDK, Supplier Part Number 1=445-9819-1-ND, TempCo=X7R, Tolerance_%=10%, Value2=25V, ValueDisplayed=1µF
C2 C3: library part CMP-0007189-1, "CAP, CERM, 1600 pF, 50 V, +/- 5%, C0G/NP0, 0603", Cap_Case=0603, Manufacturer=MuRata, Supplier Part Number 1=490-1456-1-ND, TempCo=C0G/NP0, Tolerance_%=5%, Value1=Unknown, Value2=50V, ValueDisplayed=1600pF
C5 C10 C12 C14 C21 C23: library part CMP-0007214-4, "CAP, CERM, 39 pF, 50 V, +/- 5%, C0G/NP0, 0603", Cap_Case=0603, Manufacturer=MuRata, Supplier Part Number 1=490-1417-1-ND, TempCo=C0G/NP0, Tolerance_%=5%, Value1=Unknown, Value2=50V, ValueDisplayed=39pF
C15: library part CMP-0007501-1, "CAP, CERM, 10 uF, 25 V, +/- 20%, X5R, 0603", Cap_Case=0603, Manufacturer=MuRata, Supplier Part Number 1=490-12323-1-ND, TempCo=X5R, Tolerance_%=20%, Value1=Unknown, Value2=25V, ValueDisplayed=10uF
C16 C20: library part CMP-0006836-1, "CAP, CERM, 0.022 uF, 50 V, +/- 10%, X7R, 0603", Cap_Case=0603, Manufacturer="Wurth Elektronik", TempCo=X7R, Tolerance_%=10%, Value1=Unknown, Value2=50V, ValueDisplayed=0.022uF
C17: library part CMP-0008280-1, "CAP, CERM, 100 uF, 6.3 V, +/- 20%, X5R, 0805", Cap_Case=0805, Manufacturer=MuRata, TempCo=X5R, Tolerance_%=20%, Value1=Unknown, Value2=6.3V, ValueDisplayed=100uF
C19: library part CMP-0007987-2, "CAP, CERM, 10 uF, 25 V, +/- 10%, X5R, 0805", Cap_Case=0805, Manufacturer="Samsung Electro-Mechanics", TempCo=X5R, Tolerance_%=10%, Value1=Unknown, Value2=25V, ValueDisplayed=10uF
C22: library part CMP-0083986-1, "CAP, Film, 20 µF, 900 V,+/- 10%, 0.0055 ohm, TH", Cap_Case=42.5x30x45mm, Manufacturer=AVX, Tolerance_%=10%, Value1="0.0055 ohm", Value2=900V, ValueDisplayed=20µF
C25: library part CMP-0010059-2, "CAP, AL, 150 uF, 600 V, +/- 20%, TH", Cap_Case=30x50mm, Manufacturer=Nichicon, Supplier Part Number 1=493-14697-ND, Tolerance_%=20%, Value1=Unknown, Value2=600V, ValueDisplayed=150uF
CIN3 CIN4 COUT3 COUT4: library part CMP-0009455-2, "CAP, CERM, 0.1 uF, 630 V, +/- 10%, X7R, 1812", Cap_Case=1812, Manufacturer=MuRata, Supplier Part Number 1=490-3518-1-ND, TempCo=X7R, Tolerance_%=10%, Value1=Unknown, Value2=630V, ValueDisplayed=0.1uF
D1 D3: library part CMP-0028458-1, "Diode, Schottky, 30 V, 0.2 A, SOD-323", Manufacturer="Diodes Inc.", Supplier Part Number 1=BAT54WS-FDICT-ND, Value1=0.2A, Value2=0.7V
FID1 FID2 FID3 FID4 FID5 FID6 FID7 FID8: library part CMP-0077181-1, "Fiducial mark.  There is nothing to buy or mount.", Manufacturer=N/A
H1 H8 H9 H10 H11 H12: library part CMP-0003994-1, Manufacturer=Keystone, Supplier Part Number 1=36-3484-ND
H2 H3 H4 H5 H6 H7: library part CMP-0003715-1, "MACHINE SCREW PAN PHILLIPS 4-40", Manufacturer="B&F Fastener Supply", Supplier Part Number 1=H703-ND
H13: library part CMP-0003617-1, "Machine Screw, Round, #4-40 x 1/4, Nylon, Philips panhead", Manufacturer="B&F Fastener Supply", Supplier Part Number 1=H542-ND
H14: library part CMP-0003610-1, Manufacturer=Keystone, Supplier Part Number 1=36-1902C-ND
HS_FET_PWM LS_FET_PWM PWM_HS PWM_LS: library part CMP-0055144-1, "Test Point, Compact, White, TH", Color=White, Manufacturer=Keystone, Supplier Part Number 1=36-5007-ND
HS_FLT LS_FLT: library part CMP-0002902-2, "LED, Red, SMD", Color=Red, Manufacturer=OSRAM, Value1=W, Value2=1.8V
HS_OC LS_OC: library part CMP-0002977-1, "LED, Yellow, SMD", Color=yellow, Manufacturer=Rohm, Power_TotalModule=54mW, Supplier Part Number 1=511-1588-1-ND, Value1=0.054W, Value2=2.2V
HVBUS1 HVBUS2 PGND1 PGND2 SW1 SW2: library part CMP-0055026-1, Manufacturer=Mill-Max, Supplier Part Number 1=0312-015153427100-ND
J1 J9: library part CMP-0055342-2, "Terminal Block, 5.08mm, 2x1, TH", Color=Black, Current_A=15A, Manufacturer=Molex, Supplier Part Number 1=WM7853-ND, Voltage_V=300V
J2 J4: library part CMP-0075413-2, "Header, 100mil, 6x1, Gold, TH", Color=Black, Current_A=6.3A, Manufacturer=Samtec, Supplier Part Number 1=SAM1029-06-ND, Voltage_V=550V
J3 J8: library part CMP-0055424-1, "Connector, TH, BNC", Manufacturer="Amphenol Connex", Supplier Part Number 1=ACX1051-ND
J6 J12: library part CMP-0054974-1, "Terminal Block, 2x1, 2.54mm, TH", Manufacturer="TE Connectivity", Supplier Part Number 1=A98333-ND
J7 J14 J15: library part CMP-0075407-2, "Header, 100mil, 3x1, Gold, TH", Color=Black, Current_A=6.3A, Manufacturer=Samtec, Supplier Part Number 1=SAM1029-03-ND, Voltage_V=550V
J10 J11 J13: library part CMP-0075405-2, "Header, 100mil, 2x1, Gold, TH", Color=Black, Current_A=6.3A, Manufacturer=Samtec, Supplier Part Number 1=SAM1029-02-ND, Voltage_V=550V
J16 J17 J18: library part CMP-0055388-2, "Standard Banana Jack, Uninsulated", Manufacturer="Pomona Electronics", Supplier Part Number 1=501-1115-ND
J19 J20 J21 J22 J23 J24 J25 J26 J27 J28 J29 J30: library part CMP-0120348-1, "Pin Receptacle Connector 0.025\" ~ 0.037\" (0.64mm ~ 0.94mm) No Tail Solder", Current_A=4.5A, Digikey Part Number=ED90333-ND, Manufacturer=Mill-Max, Mouser Part Number=575-030520, Operating Temperature Range="-55°C to +125°C"
L2: library part CMP-0090191-1, "INDUCTOR 570uH 13A", Manufacturer="Wurth Electronics", Operating Temperature Range="-40°C to +85°C", Test Frequency=100kHz, Tolerance_%=10%
L3: library part CMP-0012771-2, "Coupled inductor, 47 uH, 1.14 A, 0.4825 ohm, SMD", Manufacturer=Coiltronics, Supplier Part Number 1=513-1248-1-ND, ValueDisplayed=47uH
LBL1: library part THT-13-457-10, "Thermal Transfer Printable Labels, 1.250\" W x 0.250\" H - 10,000 per roll", Manufacturer=Brady, Supplier Part Number 1=04H3909
Logo1: library part CMP-0074838-1, "Texas Instrument Corporate Signature"
LOGO2: library part CMP-0074835-1, "IEC 61010-1 High Voltage Warning"
Logo3: library part CMP-0074847-1, "FCC_disclaimer"
Logo4: library part CMP-0074769-1
LOGO6: library part CMP-0074844-1
LOGO7: library part CMP-0074837-1, "IEC 61010-1 Hot Surface Warning"
R1 R5 R29 R30: library part CMP-0025797-4, "RES, 3.3 k, 5%, 0.1 W, AEC-Q200 Grade 0, 0603", Manufacturer=Vishay-Dale, Power_W=100mW, Supplier Part Number 1=541-3.3KGCT-ND, TempCo="200 ppm/C", Tolerance_%=5%, Value2=0.1W, Value_Code=3k30, ValueDisplayed=3.3k
R2 R4 R9: library part CMP-0025697-4, "RES, 0, 5%, 0.1 W, AEC-Q200 Grade 0, 0603", Manufacturer=Vishay-Dale, Power_W=100mW, Supplier Part Number 1=541-0.0GCT-ND, TempCo="200 ppm/C", Tolerance_%=5%, Value2=0.1W, Value_Code=0000, ValueDisplayed=0
R3 R15: library part CMP-0002062-2, "Trimmer, 5 K, 0.25 W, SMD", Manufacturer=Bourns, Supplier Part Number 1=3224X-1-502ECT-ND
R6 R22: library part CMP-0082530-1, "RES, 100 k, 5%, 0.1 W, 0603", Manufacturer=Vishay-Dale, Power_W=100mW, Supplier Part Number 1=541-3992-1-ND, TempCo="200 ppm/C", Tolerance_%=5%, Value2=0.1W, Value_Code=100k
R7 R21: library part CMP-0025700-4, "RES, 100, 5%, 0.1 W, AEC-Q200 Grade 0, 0603", Manufacturer=Vishay-Dale, Power_W=100mW, Supplier Part Number 1=541-100GCT-ND, TempCo="200 ppm/C", Tolerance_%=5%, Value2=0.1W, Value_Code=100R, ValueDisplayed=100
R8 R27: library part CMP-0022739-4, "RES, 105 k, 1%, 0.1 W, 0603", Manufacturer=Yageo, Power_W=100mW, Supplier Part Number 1=311-105KHRCT-ND, TempCo="100 ppm/C", Tolerance_%=1%, Value2=0.1W, Value_Code=105k
R10 R11 R12 R13 R14 R16 R17 R18 R19 R20: library part CMP-0018654-3, "RES, 30 k, 5%, 0.25 W, AEC-Q200 Grade 0, 1206", Manufacturer=Vishay-Dale, Power_W=250mW, Supplier Part Number 1=541-30KECT-ND, TempCo="200 ppm/C", Tolerance_%=5%, Value2=0.25W, Value_Code=30k0, ValueDisplayed=30k
R25: library part CMP-0023248-5, "RES, 6.20 k, 1%, 0.1 W, 0603", Manufacturer=Yageo, Power_W=100mW, Supplier Part Number 1=311-6.20KHRCT-ND, TempCo="100 ppm/C", Tolerance_%=1%, Value2=0.1W, Value_Code=6k20, ValueDisplayed=6.20k
R26: library part CMP-0022869-5, "RES, 1.18 k, 1%, 0.1 W, 0603", Manufacturer=Yageo, Power_W=100mW, Supplier Part Number 1=311-1.18KHRCT-ND, TempCo="100 ppm/C", Tolerance_%=1%, Value2=0.1W, Value_Code=1k18, ValueDisplayed=1.18k
R28: library part CMP-0024126-1, "RES, 33.2 k, 0.1%, 0.1 W, 0603", Manufacturer="Yageo America", Power_W=100mW, TempCo="25 ppm/C", Tolerance_%=0.1%, Value2=0.1W, Value_Code=33k2, ValueDisplayed=33.2k
R31: library part CMP-0025734-4, "RES, 1.6 k, 5%, 0.1 W, AEC-Q200 Grade 0, 0603", Manufacturer=Vishay-Dale, Power_W=100mW, Supplier Part Number 1=541-1.6KGCT-ND, TempCo="200 ppm/C", Tolerance_%=5%, Value2=0.1W, Value_Code=1k60, ValueDisplayed=1.6k
SH-J1 SH-J2 SH-J3 SH-J4 SH-J5: library part CMP-0003623-3, "Shunt, 100mil, Gold plated, Black", Alternate Manufacturer=3M, Alternate PartNumber=969102-0000-DA, Manufacturer=Samtec, Supplier Part Number 1=SAM8858-ND
U1 U2: library part CMP-0051803-1, "Automotive Catalog Dual 2-Input Positive-AND Gate, DCT0008A, LARGE T&R", F @ Nom Voltage(Max)(Mhz)=150, Generic Part Number=SN74LVC2G08-Q1, ICC @ Nom Voltage(Max)(mA)=0.01, Manufacturer="Texas Instruments", Operating Temperature Range(C)="-40 to 85", Rating=Automotive, tpd @ Nom Voltage(Max)(ns)=9,5.1,4.7,3.8, Voltage(Nom)(V)=1.8,2.5,3.3,5
U3 U5: library part CMP-0051969-2, "Triple Schmitt-Trigger Inverter, DCU0008A (VSSOP-8)", F @ Nom Voltage(Max)(Mhz)=150, Generic Part Number=SN74LVC3G14, ICC @ Nom Voltage(Max)(mA)=0.01, Manufacturer="Texas Instruments", Operating Temperature Range="-40 to 125 C", Rating=Catalog, tpd @ Nom Voltage(Max)(ns)=9.2,5.7,5.4,4.3, Voltage(Nom)(V)=1.8,2.5,3.3,5
U4: library part CMP-0072360-1, "3A SIMPLE SWITCHER® Power Module with 20V Maximum Input Voltage for Military and Rugged Applications, 7 pin TO-PMOD", Manufacturer="Texas Instruments", PackageTopMarking=NSUZXYTTE#*LMZ12003*EXT, PowerWise=Y
ZZ1: library part AssemblyNoteLabel, Alternate Manufacturer=-
ZZ2 ZZ3 ZZ4: library part AssemblyNote, Alternate Manufacturer=-

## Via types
v1: diameter 34, hole 16, Top Layer to Bottom Layer, 411 vias

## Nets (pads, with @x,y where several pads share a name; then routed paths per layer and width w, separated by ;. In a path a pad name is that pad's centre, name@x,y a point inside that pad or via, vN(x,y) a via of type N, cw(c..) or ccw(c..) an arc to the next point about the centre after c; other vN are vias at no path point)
5V: 5V.1 C1.2 C8.1 C9.2 C16.1 C17.1 HS_FLT.1 HS_OC.1 J12.2 J20.1 LS_FLT.1 LS_OC.1 R6.1 R22.2 R25.2 R31.2 U1.8 U2.8 U3.8 U4.7 U5.8 | length 6115.9
  Top Layer w10: v1(1890,2530) v1@1890,2540.47 ; LS_OC.1@2245.39,3401.06 LS_OC.1@2253.52,3392.93 ; HS_OC.1@2889.39,3401.06 HS_OC.1@2897.52,3392.93
  Top Layer w20: J12.2@1715.47,3410 1715.47,3224.53 5V.1@1775,3165 ; R31.2@1850,2896.97 1890,2896.97 v1@1890,2540.47 ; v1(1890,2530) 1890,2487.13 2392.22,2487.13 v1(2391,2485.91) ; v1(2030,3240) 2465.24,3240 v1(2560,3334.76) ; LS_FLT.1@2180.53,3401.06 2215,3401.06 ; 2215,3250 2215,3401.06 ; LS_OC.1@2245.39,3401.06 2215,3401.06 ; v1(2393.96,2365) 2398.96,2360 v1(2956.25,2360) ; v1(2759.88,3260) 2815,3260 2850,3295 v1(2850,3325) ; HS_FLT.1@2799.53,3401.06 v1(2850,3401.06) HS_OC.1@2889.39,3401.06 ; HS_OC.1@2897.52,3392.93 3098.96,3191.5 v1(3210,3191.5)
  Top Layer w25: U4.7@1550.47,3034.37 1550.47,2986.5 1571.97,2965 R25.2@1571.97,2905 1646.97,2905 C16.1@1650.47,2901.5 1738.98,2901.5 C17.1@1745.47,2895 ; 5V.1@1775,3165 1745.47,3135.47 C17.1@1745.47,2895 ; R31.2@1845.47,2901.5 1838.98,2895 C17.1@1745.47,2895
  Bottom Layer w10: 3325,3191.5 3325.91,3190.59
  Bottom Layer w20: 5V.1@1775,3165 1850,3240 v1(2030,3240) ; v1(1890,2530) 1935,2530 ; U5.8@1935.66,2550.55 1935.66,2530.66 1935,2530 ; C9.2@2099.82,2727.28 2187.72,2727.28 2210,2705 2210,2571.5 2168.5,2530 2130,2530 ; 2131.31,2545.63 2131.31,2531.31 2130,2530 ; v1(2391,2485.91) 2391,2362.05 v1(2393.96,2365) ; v1(2560,3334.76) 2654.4,3334.76 2729.17,3260 v1(2759.88,3260) ; v1(2850,3325) v1(2850,3401.06) ; v1(2956.25,2360) 2957.15,2360.9 3001.57,2360.9 3005.68,2365 J20.1@3140,2365 ; v1(3210,3191.5) R22.2@3270,3191.5 3325,3191.5 R6.1@3377.9,3191.5 ; U2.8@3281.5,2810.4 3325,2853.9 C1.2@3325,2875 3325,2955.26 3352.37,2982.63 3352.37,3024 ; U1.8@3281.5,3027.99 3284.56,3031.06 3345.31,3031.06 3352.37,3024 ; 3325.91,3190.59 3325.91,3080.46 3352.37,3054 3352.37,3024 ; 1935,2530 2130,2530
12V: 12V.1 C6.1 C15.1 J15.2 J26.1 L3.1 R28.1 U4.1 | length 6461.6
  Top Layer w20: L3.1@1116.93,3367.44 1116.93,3090.04 1135.47,3071.5 1250.47,3071.5 U4.1@1250.47,3034.37 ; U4.1@1250.47,3030 1250.47,2957.17 1193.98,2900.67 R28.1@1193.98,2900 C15.1@1193.98,2830 1187.53,2823.55 772.25,2823.55 755.18,2806.48 J15.2@755.18,2755 755.18,2215 1112.86,2215 1148.62,2179.23 1229.23,2179.23 1262.11,2212.11 1976.93,2212.11 2014.03,2175 2082.89,2175 2120,2212.11 2612.89,2212.11 3057.49,1767.51 v1(3574.7,1767.51) ; v1(3395,2365) v1(3565,2365)
  Bottom Layer w20: 12V.1@372.68,2950 372.68,2829.37 602.05,2600 755.1,2600 755.18,2600.08 J15.2@755.18,2755 ; J26.1@3240,2365 v1(3395,2365) ; v1(3565,2365) 3565,1781 3574.7,1771.3 v1(3574.7,1767.51)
